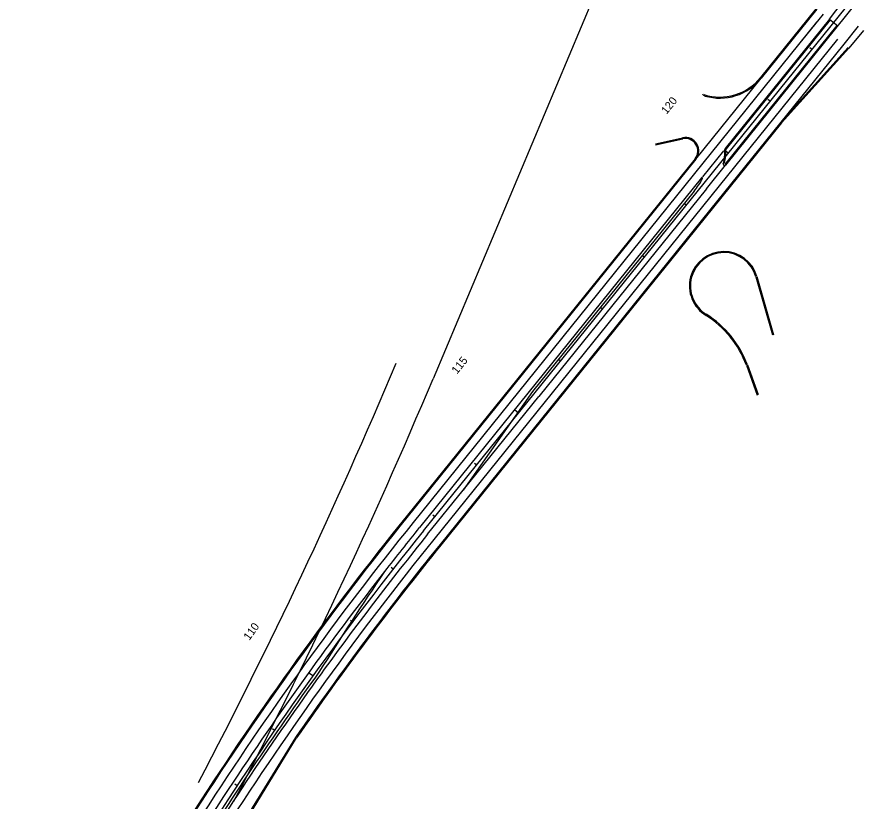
# Model space of a CAD drawing. Extents: x 2338610 to 2351914, y 366540 to 376484.
# Drawn here: x 2345450 to 2346711, y 367449 to 368623 of the extents above; entities that cross this region are included whole.
import ezdxf

# ---------------------------------------------------------------- set-up
doc = ezdxf.new("R2010")
doc.units = 0
for name, color, linetype in [('RD_HC_Cl', 7, 'Continuous'), ('RD_PD_Final_LnLine', 7, 'Continuous'), ('RD_PD_Final_TrvlWay', 7, 'Continuous'), ('RD_PD_FOC', 7, 'Continuous'), ('RD_PD_PaveShd', 7, 'Continuous'), ('TR SN UNASSIGNED 7', 7, 'Continuous')]:
    doc.layers.add(name, color=color, linetype=linetype)

msp = doc.modelspace()

# ---------------------------------------------------------------- linework, layer by layer
at = {"layer": 'RD_HC_Cl'}
for p, q in [((2346414.9, 368892.2), (2346073.6, 368081.3)), ((2346414.9, 368892.2), (2346073.6, 368081.3)), ((2346414.9, 368892.2), (2346073.6, 368081.3)), ((2346414.9, 368892.2), (2346073.6, 368081.3)), ((2346059.3, 367853.2), (2346703.6, 368651.5)), ((2346658.3, 368627.2), (2346625.9, 368587.1)), ((2346710.6, 368609.3), (2346688.9, 368582.4))]:
    msp.add_line(p, q, dxfattribs=at)
for centre, radius, start, end in [((2338460.5, 371285.5), 8200, 332.32074, 337.175), ((2338460.5, 371285.5), 8200, 332.32074, 337.175), ((2338460.5, 371285.5), 8200, 332.32074, 337.175), ((2338460.5, 371285.5), 8200, 332.32074, 337.175), ((2338460.5, 371285.5), 8260, 332.32074, 337.175), ((2338460.5, 371285.5), 8260, 332.32074, 337.175), ((2338460.5, 371285.5), 8260, 332.32074, 337.175), ((2338460.5, 371285.5), 8260, 332.32074, 337.175), ((2349947, 364715.5), 4996, 141.0938, 153.6971)]:
    msp.add_arc(centre, radius, start, end, dxfattribs=at)
at = {"layer": 'RD_PD_Final_LnLine'}
for p, q in [((2346648.9, 368634.7), (2346565.4, 368531.3)), ((2346648.4, 368615), (2346043.7, 367865.7)), ((2346710.6, 368609.3), (2346688.9, 368582.4)), ((2346679.6, 368589.9), (2346074.8, 367840.6)), ((2346688.9, 368582.4), (2346487.8, 368333.2)), ((2346594.7, 368465.7), (2346695.6, 368577.1)), ((2346467.4, 368409.9), (2346565.4, 368531.3)), ((2346406.8, 368432.9), (2346447.5, 368441.9)), ((2346508.7, 368422.7), (2346477.2, 368383.8)), ((2346467.4, 368409.9), (2346034.4, 367873.3)), ((2346483.2, 368365.7), (2346511.9, 368401.3)), ((2346483.2, 368365.7), (2346232, 368054.4)), ((2346487.8, 368333.2), (2346084.2, 367833.1)), ((2346118.9, 367914.4), (2346232, 368054.4)), ((2345789.2, 367416.2), (2345867.8, 367544))]:
    msp.add_line(p, q, dxfattribs=at)
for centre, radius, start, end in [((2346503.2, 368581.5), 80, 253.9065, 321.0938), ((2346482.4, 368509.5), 5, 195.865, 253.9065), ((2346451.9, 368422.4), 20, 321.0938, 102.484), ((2349947, 364715.5), 5028, 141.0938, 153.3996), ((2349947, 364715.5), 5016, 141.0938, 153.4055), ((2349947, 364715.5), 4976, 141.0938, 153.4002), ((2349947, 364715.5), 4964, 141.0938, 145.2627), ((2349947, 364715.5), 5004, 142.0511, 144.1409), ((2349947, 364715.5), 5004, 144.1409, 148.8707)]:
    msp.add_arc(centre, radius, start, end, dxfattribs=at)
at = {"layer": 'RD_PD_Final_TrvlWay'}
for p, q in [((2346709.8, 368646.5), (2346511.9, 368401.3)), ((2346667.6, 368619.7), (2346511.2, 368425.8)), ((2346475.8, 368382), (2346053.1, 367858.2)), ((2346465, 368362.3), (2346222.6, 368062)), ((2346557.3, 368234), (2346582.3, 368146.8)), ((2346544.6, 368101.8), (2346560.8, 368057.4)), ((2346222.6, 368062), (2346118.9, 367914.4)), ((2346065.5, 367848.2), (2346118.9, 367914.4))]:
    msp.add_line(p, q, dxfattribs=at)
for centre, radius, start, end in [((2346182, 369011.6), 624, 321.0938, 53.1918), ((2346448.3, 368420.3), 62.6, 343.9661, 3.6972), ((2346512.7, 368424.6), 2, 141.0938, 186.6668), ((2346510.4, 368402.6), 2, 166.9357, 321.0938), ((2346365.5, 368442.2), 127.6, 321.2453, 331.2935), ((2346476.6, 368381.4), 1, 331.2935, 141.0938), ((2346509.3, 368220.2), 50, 15.9925, 239.3979), ((2346403.7, 368050.3), 150, 20.0868, 58.132), ((2349947, 364715.5), 5004, 141.0938, 142.0511), ((2349947, 364715.5), 4988, 141.0938, 144.1121), ((2350128, 364994.9), 4985.9, 145.8645, 147.9351), ((2349947, 364715.5), 4992, 144.1121, 148.1246), ((2349947, 364715.5), 4988, 144.1121, 148.3622)]:
    msp.add_arc(centre, radius, start, end, dxfattribs=at)
at = {"layer": 'RD_PD_FOC'}
for p, q in [((2346647.8, 368635.7), (2346564.3, 368532.2)), ((2346668.8, 368618.7), (2346512.7, 368425.4)), ((2346678.9, 368610.5), (2346512.3, 368404.1)), ((2346595.9, 368464.7), (2346696.7, 368576.1)), ((2346595.9, 368464.7), (2346429.2, 368258.2)), ((2346407.1, 368431.5), (2346447.9, 368440.5)), ((2346466.3, 368410.8), (2346033.2, 367874.2)), ((2346429.2, 368258.2), (2346395.4, 368216.4)), ((2346558.8, 368234.4), (2346583.8, 368147.2)), ((2346395.4, 368216.4), (2346085.3, 367832.1)), ((2346543.1, 368101.3), (2346559.4, 368056.8)), ((2345790.5, 367415.4), (2345869, 367543.2))]:
    msp.add_line(p, q, dxfattribs=at)
for centre, radius, start, end in [((2346503.2, 368581.5), 78.5, 252.3972, 321.0938), ((2346451.9, 368422.4), 18.5, 321.0938, 102.484), ((2346448.3, 368420.3), 64.1, 346.1411, 3.2809), ((2346514.3, 368424.1), 2, 141.0938, 183.2809), ((2346511.5, 368404.7), 1, 166.1411, 321.0938), ((2346509.3, 368220.2), 51.5, 15.9925, 239.3979), ((2346403.7, 368050.3), 148.5, 20.0868, 58.132), ((2349947, 364715.5), 5029.5, 141.0938, 153.3986), ((2349947, 364715.5), 4962.5, 141.0938, 145.2627)]:
    msp.add_arc(centre, radius, start, end, dxfattribs=at)
at = {"layer": 'RD_PD_PaveShd'}
for p, q in [((2346667.6, 368619.7), (2346680, 368609.6)), ((2346718.4, 368603), (2346696.7, 368576.1))]:
    msp.add_line(p, q, dxfattribs=at)
at = {"layer": 'TR SN UNASSIGNED 7'}
for p, q in [((2346641.5, 368574.5), (2346638.3, 368577)), ((2346578.7, 368496.7), (2346575.5, 368499.2)), ((2346515.8, 368418.9), (2346509.6, 368423.9)), ((2346453, 368341.1), (2346449.9, 368343.6)), ((2346390.2, 368263.3), (2346387.1, 368265.8)), ((2346327.4, 368185.4), (2346324.3, 368188)), ((2346264.6, 368107.6), (2346261.5, 368110.1)), ((2346201.8, 368029.8), (2346195.6, 368034.8)), ((2346139, 367952), (2346135.9, 367954.5)), ((2346076.2, 367874.2), (2346073.1, 367876.7)), ((2346013.8, 367796), (2346010.7, 367798.5)), ((2345953, 367716.7), (2345949.8, 367719.1)), ((2345893.7, 367636.1), (2345887.2, 367640.8)), ((2345836, 367554.4), (2345832.8, 367556.7)), ((2345780, 367471.6), (2345776.7, 367473.8))]:
    msp.add_line(p, q, dxfattribs=at)

# ---------------------------------------------------------------- texts
for s, rotation, p in [('120', 51.0938, (2346423.5, 368476.4)), ('115', 51.0938, (2346109.5, 368087.4)), ('110', 54.2249, (2345798.3, 367688.5))]:
    msp.add_text(s, height=12, rotation=rotation, dxfattribs=at).set_placement(p)

doc.saveas('drawing.dxf')
